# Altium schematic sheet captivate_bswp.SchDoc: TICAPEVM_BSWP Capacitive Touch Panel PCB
size Letter; Date: Not shown in title block; ApprovedBy: Not shown in title block; CheckedBy: Not shown in title block; Author: Not shown in title block; CompanyName: Not shown in title block; DrawnBy: W. Schnoor; Engineer: Not shown in title block; Organization: Not shown in title block; Address1: Not shown in title block; Address2: Not shown in title block; Address3: Not shown in title block; Address4: Not shown in title block; DocumentNumber: 1; Revision: Use project parameter SCH_Rev; SheetNumber: 1; SheetTotal: 1; PageSetup: Record=PageOptions¦CenterHorizontal=True¦CenterVertical=True¦PrintScale=1.00¦XCorrection=1.00¦YCorrection=1.00¦PrintKind=0¦BorderSize=5000000¦LeftOffset=0¦BottomOffset=0¦Orientation=2¦PaperLength=1000¦PaperWidth=1000¦Scale=100¦PaperSource=15¦PrintQuality=600¦MediaType=1¦DitherType=10¦PaperKind=Letter¦PrintScaleMode=1
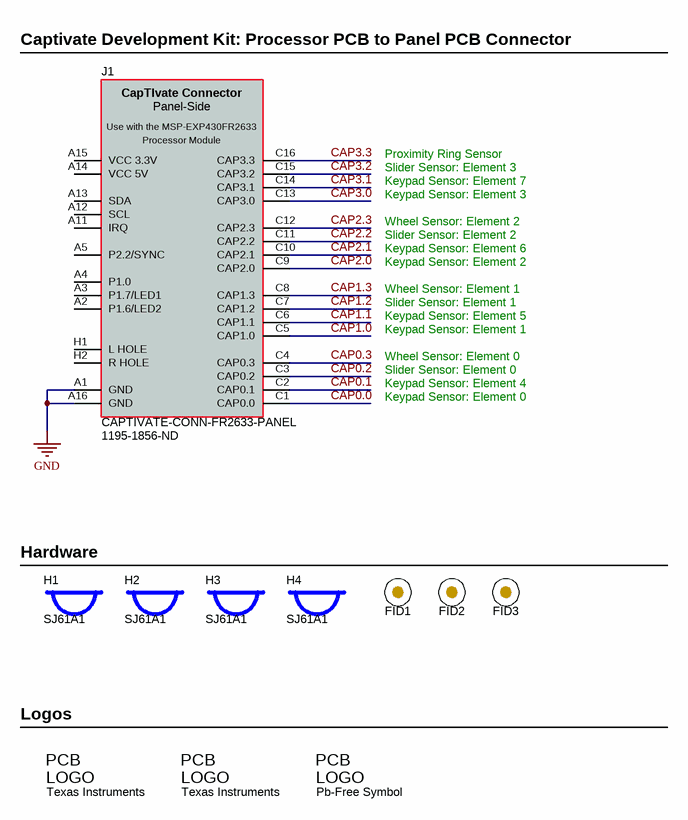
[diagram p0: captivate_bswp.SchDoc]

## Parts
FID1  Fiducial  [Fiducial10-20]  (value not drawn)
FID2  Fiducial  [Fiducial10-20]  (value not drawn)
FID3  Fiducial  [Fiducial10-20]  (value not drawn)
H1  SJ61A1  [Bumpon_SJ61A1]
H2  SJ61A1  [Bumpon_SJ61A1]
H3  SJ61A1  [Bumpon_SJ61A1]
H4  SJ61A1  [Bumpon_SJ61A1]
J1  CAPTIVATE-CONN-FR2633-PANEL  Supplier Part Number 1: 1195-1856-ND  [CAPTIVATE-CONN-48]
LeadFreeLogo  Pb-Free Symbol  [Pb-Free_Overlay_Medium]  (no BOM)
TI_LOGO_1  Texas Instruments  [TI_Horizontal_Overlay_Medium]  (no BOM)
TI_LOGO_2  Texas Instruments  [TI_Horizontal_Overlay_Medium]  (no BOM)

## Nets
GND: J1.A1(GND) J1.A16(GND)
CAP0.0: J1.C1(CAP0.0)
CAP0.1: J1.C2(CAP0.1)
CAP0.2: J1.C3(CAP0.2)
CAP0.3: J1.C4(CAP0.3)
CAP1.0: J1.C5(CAP1.0)
CAP1.1: J1.C6(CAP1.1)
CAP1.2: J1.C7(CAP1.2)
CAP1.3: J1.C8(CAP1.3)
CAP2.0: J1.C9(CAP2.0)
CAP2.1: J1.C10(CAP2.1)
CAP2.2: J1.C11(CAP2.2)
CAP2.3: J1.C12(CAP2.3)
CAP3.0: J1.C13(CAP3.0)
CAP3.1: J1.C14(CAP3.1)
CAP3.2: J1.C15(CAP3.2)
CAP3.3: J1.C16(CAP3.3)

Not connected (* = marked no-connect by the designer): J1 A2(P1.6/LED2) A3(P1.7/LED1) A4(P1.0) A5(P2.2/SYNC) A11(IRQ) A12(SCL) A13(SDA) A14(VCC_5V) A15(VCC_3.3V) H1(L_HOLE) H2(R_HOLE)

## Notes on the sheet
- Captivate Development Kit: Processor PCB to Panel PCB Connector
- Proximity Ring Sensor
- Keypad Sensor: Element 3
- Keypad Sensor: Element 7
- Slider Sensor: Element 3
- Wheel Sensor: Element 2
- Keypad Sensor: Element 2
- Keypad Sensor: Element 6
- Slider Sensor: Element 2
- Wheel Sensor: Element 1
- Keypad Sensor: Element 1
- Keypad Sensor: Element 5
- Slider Sensor: Element 1
- Wheel Sensor: Element 0
- Keypad Sensor: Element 0
- Keypad Sensor: Element 4
- Slider Sensor: Element 0
- (near H1) Hardware
- (near TI_LOGO_1) Logos

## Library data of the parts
FID1-FID3 = Fiducial: Fiducial mark.  There is nothing to buy or mount.; SymbolCreator: codlsc
H1-H4 = SJ61A1: Bumpon, Cylindrical, 0.312 X 0.200, Black; Manufacturer: 3M; SymbolCreator: a0412235
J1 = CAPTIVATE-CONN-MSP-EXP430FR2633-PANEL: CapTIvate Panel-Side Connector, 3x16, 100mil, TH, RA, M, MSP-EXP430FR2633; Manufacturer: Used in BOM report; SymbolCreator: a0273983; U/M: EA, IN, or GM
LeadFreeLogo = Pb-Free: SymbolCreator: a0412235
TI_LOGO_1 TI_LOGO_2 = TI_Logo: Texas Instrument Corporate Signature; SymbolCreator: a0412235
